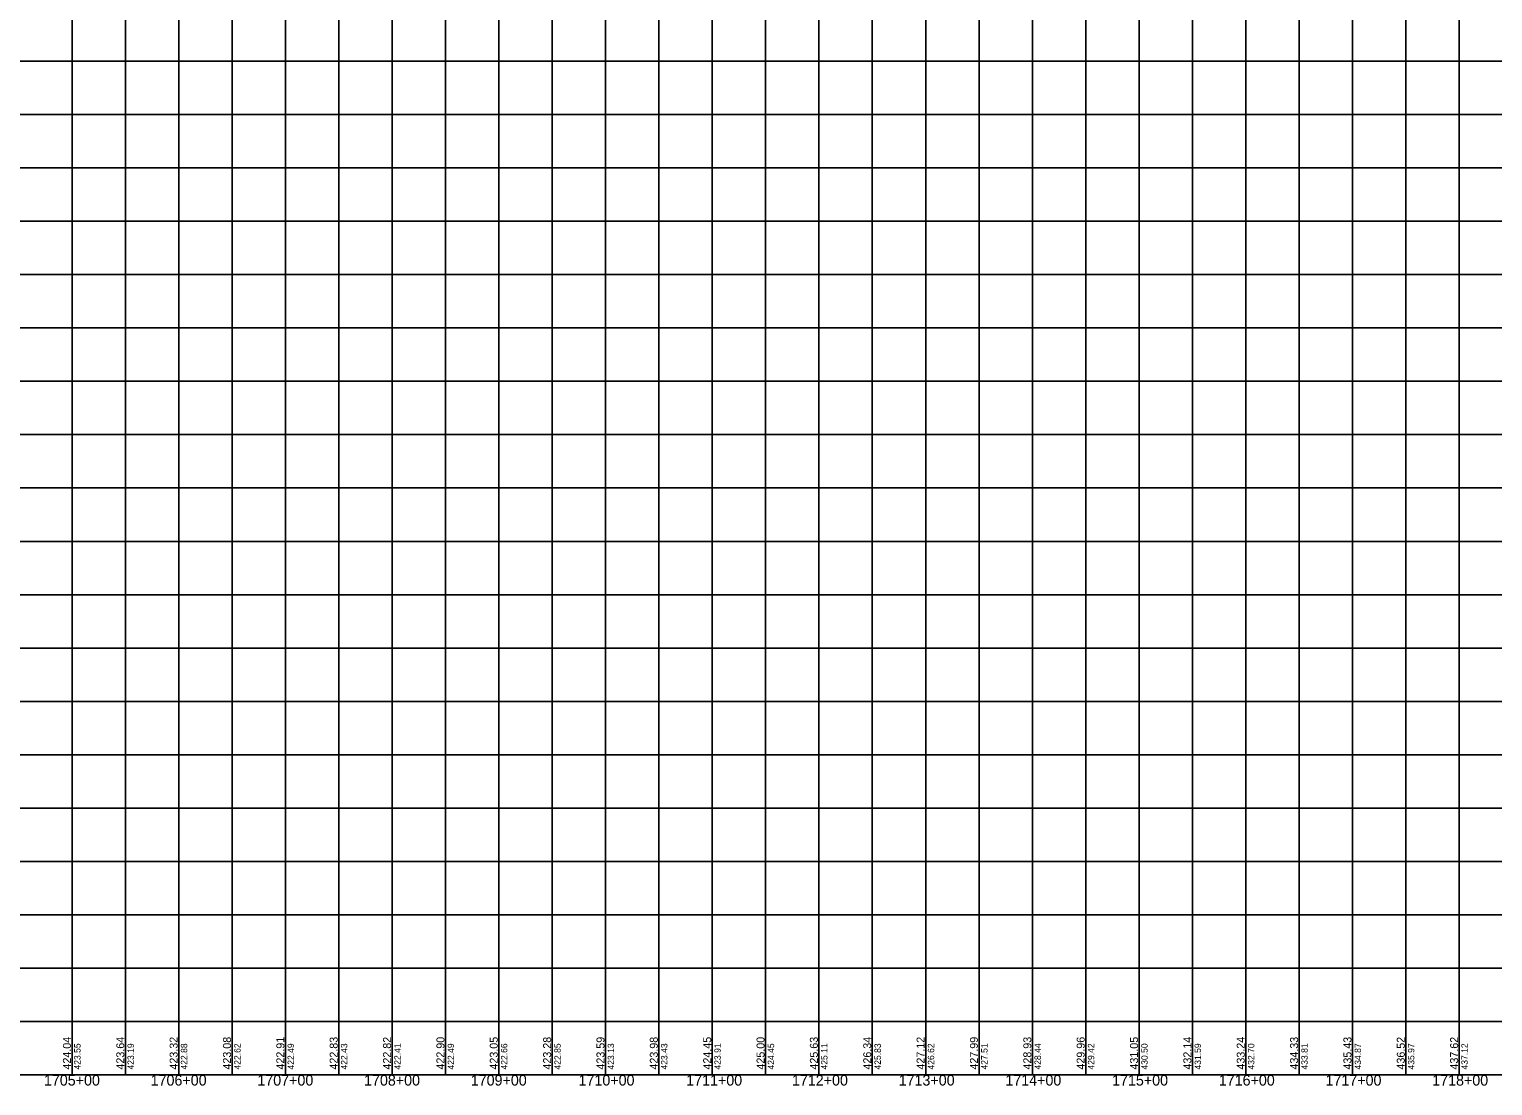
# Model space of a CAD drawing. Extents: x -90830 to 2015517, y -20856 to 836331.
# Drawn here: x 59383 to 60755, y -10807 to -9817 of the extents above; entities that cross this region are included whole.
import ezdxf

# ---------------------------------------------------------------- set-up
doc = ezdxf.new("R2010")
doc.units = 0
for name, color, linetype in [('Level 1', 7, 'Continuous'), ('RD_DDB_Profile_Elev', 7, 'Continuous'), ('RD_DDB_StaTX', 7, 'Continuous'), ('RD_DDB_StripGrade', 7, 'Continuous'), ('RD_GPK_Profile_Cell', 7, 'Continuous')]:
    doc.layers.add(name, color=color, linetype=linetype)

msp = doc.modelspace()

# ---------------------------------------------------------------- linework, layer by layer
at = {"layer": 'Level 1'}
for p, q in [((59423.5, -9797.1), (59423.5, -10297.1)), ((59473.5, -9797.1), (59473.5, -10297.1)), ((59523.5, -9797.1), (59523.5, -10297.1)), ((59573.5, -9797.1), (59573.5, -10297.1)), ((59623.5, -9797.1), (59623.5, -10297.1)), ((59673.5, -9797.1), (59673.5, -10297.1)), ((59723.5, -9797.1), (59723.5, -10297.1)), ((59773.5, -9797.1), (59773.5, -10297.1)), ((59823.5, -9797.1), (59823.5, -10297.1)), ((59873.5, -9797.1), (59873.5, -10297.1)), ((59923.5, -9797.1), (59923.5, -10297.1)), ((59973.5, -9797.1), (59973.5, -10297.1)), ((60023.5, -9797.1), (60023.5, -10297.1)), ((60073.5, -9797.1), (60073.5, -10297.1)), ((60123.5, -9797.1), (60123.5, -10297.1)), ((60173.5, -9797.1), (60173.5, -10297.1)), ((60223.5, -9797.1), (60223.5, -10297.1)), ((60273.5, -9797.1), (60273.5, -10297.1)), ((60323.5, -9797.1), (60323.5, -10297.1)), ((60373.5, -9797.1), (60373.5, -10297.1)), ((60423.5, -9797.1), (60423.5, -10297.1)), ((60473.5, -9797.1), (60473.5, -10297.1)), ((60523.5, -9797.1), (60523.5, -10297.1)), ((60573.5, -9797.1), (60573.5, -10297.1)), ((60623.5, -9797.1), (60623.5, -10297.1)), ((60673.5, -9797.1), (60673.5, -10297.1)), ((60723.5, -9797.1), (60723.5, -10297.1)), ((59173.5, -9847.1), (60773.5, -9847.1)), ((59173.5, -9897.1), (60773.5, -9897.1)), ((59173.5, -9947.1), (60773.5, -9947.1)), ((59173.5, -9997.1), (60773.5, -9997.1)), ((59173.5, -10047.1), (60773.5, -10047.1)), ((59173.5, -10097.1), (60773.5, -10097.1)), ((59173.5, -10147.1), (60773.5, -10147.1)), ((59173.5, -10197.1), (60773.5, -10197.1)), ((59173.5, -10247.1), (60773.5, -10247.1)), ((59173.5, -10297.1), (60773.5, -10297.1)), ((59173.5, -10297.1), (60773.5, -10297.1)), ((59423.5, -10297.1), (59423.5, -10797.1)), ((59473.5, -10297.1), (59473.5, -10797.1)), ((59523.5, -10297.1), (59523.5, -10797.1)), ((59573.5, -10297.1), (59573.5, -10797.1)), ((59623.5, -10297.1), (59623.5, -10797.1)), ((59673.5, -10297.1), (59673.5, -10797.1)), ((59723.5, -10297.1), (59723.5, -10797.1)), ((59773.5, -10297.1), (59773.5, -10797.1)), ((59823.5, -10297.1), (59823.5, -10797.1)), ((59873.5, -10297.1), (59873.5, -10797.1)), ((59923.5, -10297.1), (59923.5, -10797.1)), ((59973.5, -10297.1), (59973.5, -10797.1)), ((60023.5, -10297.1), (60023.5, -10797.1)), ((60073.5, -10297.1), (60073.5, -10797.1)), ((60123.5, -10297.1), (60123.5, -10797.1)), ((60173.5, -10297.1), (60173.5, -10797.1)), ((60223.5, -10297.1), (60223.5, -10797.1)), ((60273.5, -10297.1), (60273.5, -10797.1)), ((60323.5, -10297.1), (60323.5, -10797.1)), ((60373.5, -10297.1), (60373.5, -10797.1)), ((60423.5, -10297.1), (60423.5, -10797.1)), ((60473.5, -10297.1), (60473.5, -10797.1)), ((60523.5, -10297.1), (60523.5, -10797.1)), ((60573.5, -10297.1), (60573.5, -10797.1)), ((60623.5, -10297.1), (60623.5, -10797.1)), ((60673.5, -10297.1), (60673.5, -10797.1)), ((60723.5, -10297.1), (60723.5, -10797.1)), ((59173.5, -10347.1), (60773.5, -10347.1)), ((59173.5, -10397.1), (60773.5, -10397.1)), ((59173.5, -10447.1), (60773.5, -10447.1)), ((59173.5, -10497.1), (60773.5, -10497.1)), ((59173.5, -10547.1), (60773.5, -10547.1)), ((59173.5, -10597.1), (60773.5, -10597.1)), ((59173.5, -10647.1), (60773.5, -10647.1)), ((59173.5, -10697.1), (60773.5, -10697.1)), ((59173.5, -10747.1), (60773.5, -10747.1)), ((59173.5, -10797.1), (60773.5, -10797.1))]:
    msp.add_line(p, q, dxfattribs=at)
at = {"layer": 'RD_GPK_Profile_Cell'}
msp.add_line((4823.5, -10797.1), (75223.5, -10797.1), dxfattribs=at)

# ---------------------------------------------------------------- texts
at = {"layer": 'RD_DDB_Profile_Elev'}
for s, p in [('424.04', (59422.5, -10792.1)), ('423.64', (59472.5, -10792.1)), ('423.32', (59522.5, -10792.1)), ('423.08', (59572.5, -10792.1)), ('422.91', (59622.5, -10792.1)), ('422.83', (59672.5, -10792.1)), ('422.82', (59722.5, -10792.1)), ('422.90', (59772.5, -10792.1)), ('423.05', (59822.5, -10792.1)), ('423.28', (59872.5, -10792.1)), ('423.59', (59922.5, -10792.1)), ('423.98', (59972.5, -10792.1)), ('424.45', (60022.5, -10792.1)), ('425.00', (60072.5, -10792.1)), ('425.63', (60122.5, -10792.1)), ('426.34', (60172.5, -10792.1)), ('427.12', (60222.5, -10792.1)), ('427.99', (60272.5, -10792.1)), ('428.93', (60322.5, -10792.1)), ('429.96', (60372.5, -10792.1)), ('431.05', (60422.5, -10792.1)), ('432.14', (60472.5, -10792.1)), ('433.24', (60522.5, -10792.1)), ('434.33', (60572.5, -10792.1)), ('435.43', (60622.5, -10792.1)), ('436.52', (60672.5, -10792.1)), ('437.62', (60722.5, -10792.1))]:
    msp.add_text(s, height=7.5, rotation=90, dxfattribs=at).set_placement(p)
at = {"layer": 'RD_DDB_StaTX'}
for s, p in [('1705+00', (59397.2, -10807.1)), ('1706+00', (59497.2, -10807.1)), ('1707+00', (59597.2, -10807.1)), ('1708+00', (59697.2, -10807.1)), ('1709+00', (59797.2, -10807.1)), ('1710+00', (59898.2, -10807.1)), ('1711+00', (59999.1, -10807.1)), ('1712+00', (60098.2, -10807.1)), ('1713+00', (60198.2, -10807.1)), ('1714+00', (60298.2, -10807.1)), ('1715+00', (60398.2, -10807.1)), ('1716+00', (60498.2, -10807.1)), ('1717+00', (60598.2, -10807.1)), ('1718+00', (60698.2, -10807.1))]:
    msp.add_text(s, height=10, dxfattribs=at).set_placement(p)
at = {"layer": 'RD_DDB_StripGrade'}
for s, p in [('423.55', (59431.5, -10792.1)), ('423.19', (59481.5, -10792.1)), ('422.88', (59531.5, -10792.1)), ('422.62', (59581.5, -10792.1)), ('422.49', (59631.5, -10792.1)), ('422.43', (59681.5, -10792.1)), ('422.41', (59731.5, -10792.1)), ('422.49', (59781.5, -10792.1)), ('422.66', (59831.5, -10792.1)), ('422.85', (59881.5, -10792.1)), ('423.13', (59931.5, -10792.1)), ('423.43', (59981.5, -10792.1)), ('423.91', (60031.5, -10792.1)), ('424.45', (60081.5, -10792.1)), ('425.11', (60131.5, -10792.1)), ('425.83', (60181.5, -10792.1)), ('426.62', (60231.5, -10792.1)), ('427.51', (60281.5, -10792.1)), ('428.44', (60331.5, -10792.1)), ('429.42', (60381.5, -10792.1)), ('430.50', (60431.5, -10792.1)), ('431.59', (60481.5, -10792.1)), ('432.70', (60531.5, -10792.1)), ('433.81', (60581.5, -10792.1)), ('434.87', (60631.5, -10792.1)), ('435.97', (60681.5, -10792.1)), ('437.12', (60731.5, -10792.1))]:
    msp.add_text(s, height=6, rotation=90, dxfattribs=at).set_placement(p)

doc.saveas('drawing.dxf')
